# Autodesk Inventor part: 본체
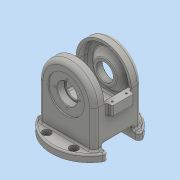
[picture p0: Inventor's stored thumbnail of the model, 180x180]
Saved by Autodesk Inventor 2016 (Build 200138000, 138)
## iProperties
Created: 2024-08
Part Number: 본체
Material: 일반
Document SubType Name: Modeling
Designer: pc-7
Density: 1 g/cm^3
Appearance: 기본값
Author: pc-7
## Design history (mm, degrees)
sketch "스케치1"
  geometry: C1 r 71 at (0, 0); 1 further point
  constraints: 1 centre point, 1 coincident
  dimensions: "d0" = 142 diameter of C1
extrude "돌출1" new body sketch "스케치1" distance "d1" = 13; taper "d2" = 0 deg
sketch "스케치2"
  geometry: L1 (-51, 81)-(51, 81); L2 (51, 81)-(51, 13); L3 (51, 13)-(-51, 13); L4 (-51, 13)-(-51, 81); L5 (71, 13)-(-71, 13) reference; L6 (-71, 0)-(71, 0) reference; A1 r 51 centre (0, 81) between (51, 81) and (-51, 81); A2 r 51 centre (0, 81) between (-51, 81) and (51, 81); 2 further points
  constraints: 8 end point, 4 point on circle, 3 midpoint, 2 centre point, 2 parallel, 1 horizontal, 1 perpendicular, 1 vertical alignment
  dimensions: "d3" = 81 distance from line of L6 A1.centre; "d4" = 102 diameter of A1
extrude "돌출2" join sketch "스케치2" stored distance "d5" = 88; taper "d6" = 0 deg
sketch "스케치3"
  geometry: L1 (19, 28)-(0, 28); L2 (0, 28)-(0, -28); L3 (0, -28)-(19, -28); L4 (19, -28)-(19, 28); 2 further points
  constraints: 8 end point, 2 parallel, 1 coincident, 1 horizontal, 1 midpoint, 1 perpendicular
  dimensions: "d7" = 19 distance between parallel lines of L2 L4; "d8" = 56 distance between parallel lines of L3 L1
extrude "돌출3" cut sketch "스케치3" stored distance "d9" = 88; taper "d10" = 0 deg
node "작업 평면1"
sketch "스케치4"
  geometry: L1 (-61, -20)-(61, -20); L2 (61, -20)-(61, 20); L3 (61, 20)-(-61, 20); L4 (-61, 20)-(-61, -20); L5 (-61, -20)-(61, 20); L6 (61, -20)-(-61, 20); 1 further point
  constraints: 12 end point, 2 midpoint, 2 parallel, 1 horizontal, 1 perpendicular
  dimensions: "d15" = 122 distance between parallel lines of L2 L4; "d16" = 40 distance between parallel lines of L1 L3
extrude "돌출4" join sketch "스케치4" distance "d17" = 20; taper "d18" = 0 deg
sketch "스케치5"
  geometry: L1 (-51, 13)-(-51, 81) reference; L2 (51, 81)-(51, 13) reference; L3 (-51, 13)-(51, 13) reference; L4 (-46, 81)-(-46, 40); L5 (46, 40)-(46, 81); L6 (65.246, 0)-(-65.246, 0) reference; L7 (-46, 40)-(46, 40); A1 r 51 centre (0, 81) between (51, 81) and (-51, 81) reference; A2 r 46 centre (0, 81) between (46, 81) and (-46, 81); 1 further point
  constraints: 6 end point, 2 point on circle, 1 centre point, 1 other
  dimensions: "d21" = 5 distance between parallel lines of L2 L5; "d22" = 40 distance from line of L6 L4.end; "d23" = 40 distance from line of L6 L5.start; "d24" = 5 distance between parallel lines of L1 L4
extrude "돌출5" cut sketch "스케치5" stored distance "d25" = 78; taper "d26" = 0 deg
sketch "스케치6"
  geometry: L1 (132, 25)-(81, 25); L2 (81, 25)-(81, -25); L3 (81, -25)-(132, -25); L4 (132, -25)-(132, 25); L5 (132, -44)-(132, 44) reference; L6 (0, -28)-(0, -71) reference; 3 further points
  constraints: 8 end point, 3 midpoint, 2 parallel, 1 horizontal, 1 horizontal alignment, 1 perpendicular
  dimensions: "d27" = 50 distance between parallel lines of L3 L1; "d28" = 81 distance between parallel lines of L6 L2
extrude "돌출6" cut sketch "스케치6" stored distance "d29" = 78; taper "d30" = 0 deg
sketch "스케치7"
  geometry: C1 r 33.5 at (0, 81); 1 further point
  constraints: 1 centre point, 1 vertical alignment
  dimensions: "d31" = 81 distance of point (0, 0) C1.centre; "d32" = 67 diameter of C1
extrude "돌출7" join sketch "스케치7" distance "d33" = 12; taper "d34" = 0 deg
feature "면 기울기1" dims angle "d35" = 45 deg
feature "면 기울기2" dims angle "d36" = 45 deg
sketch "스케치8"
  geometry: C1 r 21.5 at (0, 81) reference; 2 further points
  constraints: 1 coincident
hole "구멍1" sketch "스케치8" at (0, 81) diameter "d37" = 37; stored, may be unused: countersink angle "d41" = 90 deg, drill point angle "d43" = 0 deg; dims "d38" = 6, "d39" = 67, "d40" = 2, "d42" = 15
hole "구멍2" diameter "d46" = 32; stored, may be unused: countersink angle "d50" = 90 deg, drill point angle "d52" = 0 deg; dims "d44" = 10, "d45" = 10, "d47" = 6, "d48" = 67, "d49" = 2, "d51" = 15
sketch "스케치9"
  geometry: C1 r 30 at (0, 0); 1 further point
  constraints: 1 centre point, 1 coincident
  dimensions: "d53" = 60 diameter of C1
extrude "돌출8" cut sketch "스케치9" distance "d54" = 22; taper "d55" = 0 deg
hole "구멍3" diameter "d58" = 22; stored, may be unused: countersink angle "d62" = 90 deg, drill point angle "d64" = 0 deg; dims "d56" = 10, "d57" = 10, "d59" = 6, "d60" = 28, "d61" = 15, "d63" = 15
sketch "스케치10" dims "d65" = 46
  geometry: L1 (-51, 0)-(-51, -68) reference; L2 (51, -68)-(-51, -68) reference; L3 (51, -68)-(51, 0) reference; C1 r 33.5 at (0, 0) reference; A1 r 51 centre (0, 0) between (51, 0) and (-51, 0) reference; 3 further points
  constraints: 2 vertical alignment, 1 coincident, 2 other
hole "구멍4" sketch "스케치10" at (0, 23) diameter "d66" = 3.242; stored, may be unused: countersink angle "d70" = 90 deg, drill point angle "d72" = 118 deg; dims "d67" = 8, "d68" = 28, "d69" = 15, "d71" = 10
sketch "스케치11"
  geometry: 2 further points
  dimensions: "d76" = 13 vertical distance of point (0, 0) point (-54, 13); "d77" = 54 horizontal distance of point (-54, 13) point (0, 0)
hole "구멍5" sketch "스케치11" at (-54, 13) diameter "d78" = 3.242; stored, may be unused: countersink angle "d82" = 90 deg, drill point angle "d84" = 118 deg; dims "d79" = 8, "d80" = 28, "d81" = 15, "d83" = 10
sketch "스케치12" dims "d91" = 46
  geometry: 3 further points
  constraints: 2 vertical alignment, 1 coincident, 2 other
hole "구멍6" sketch "스케치12" at (0, 23) diameter "d92" = 3.242; stored, may be unused: countersink angle "d96" = 90 deg, drill point angle "d98" = 118 deg; dims "d93" = 8, "d94" = 28, "d95" = 15, "d97" = 10
sketch "스케치13"
  geometry: 2 further points
  dimensions: "d102" = 25 horizontal distance of point (0, 0) point (-25, -55); "d103" = 55 vertical distance of point (0, 0) point (-25, -55)
hole "구멍7" sketch "스케치13" at (-25, -55) diameter "d104" = 9; stored, may be unused: countersink angle "d108" = 90 deg, drill point angle "d110" = 0 deg; dims "d105" = 8, "d106" = 15, "d107" = 8.8, "d109" = 10
fillet "모깎기1" dims "d117" = 6
fillet "모깎기2" dims "d118" = 8
fillet "모깎기3" dims "d119" = 3
fillet "모깎기4" dims "d120" = 3
fillet "모깎기5" dims "d121" = 3
fillet "모깎기6" dims "d122" = 3
fillet "모깎기7" dims "d123" = 3
fillet "모깎기8" dims "d124" = 3
fillet "모깎기9" dims "d125" = 3
fillet "모깎기10" dims "d126" = 3
fillet "모깎기11" dims "d127" = 3
fillet "모깎기12" dims "d128" = 3
fillet "모깎기13" dims "d129" = 3
fillet "모깎기14" dims "d130" = 3
chamfer "모따기1" distance "d131" = 1; stored, may be unused: second distance "d132" = 2, angle "d133" = 45 deg
chamfer "모따기2" distance "d134" = 1; stored, may be unused: second distance "d135" = 2, angle "d136" = 45 deg
chamfer "모따기3" distance "d137" = 1; stored, may be unused: second distance "d138" = 2, angle "d139" = 45 deg
fillet "모깎기15" dims "d140" = 0.3
fillet "모깎기16" dims "d141" = 0.3
fillet "모깎기17" dims "d142" = 3
fillet "모깎기18" dims "d143" = 3
fillet "모깎기19" dims "d144" = 3
sketch "스케치14"
  geometry: L1 (-24.887, 33.602)-(24.887, 33.602); L2 (24.887, 33.602)-(24.887, 26.398); L3 (24.887, 26.398)-(-24.887, 26.398); L4 (-24.887, 26.398)-(-24.887, 33.602); L5 (-24.887, 30)-(24.887, 30); L6 (0, 33.602)-(0, 26.398); L7 (-60.512, 0)-(60.512, 0) reference; 3 further points
  constraints: 6 midpoint, 4 end point, 1 vertical alignment, 2 other
  dimensions: "d145" = 30 distance from line of L7 point (0, 30)
feature "엠보싱1" sketch "스케치14" dims "d7" = 19, "d8" = 56, "d146" = 0.5, "d147" = 0
node "솔리드1"
mirror "대칭1"
mirror "대칭2"
pattern_circular "원형 패턴1" dims angle "d74" = 360 deg
mirror "대칭3"
pattern_linear "직사각형 패턴1" dims "d87" = 26
pattern_linear "직사각형 패턴2" dims "d90" = 108
pattern_circular "원형 패턴2" dims angle "d100" = 360 deg
pattern_linear "직사각형 패턴3" dims "d113" = 50
node "투영된 루프1"
node "투영된 루프2"
other parameters: "d11" = 68
